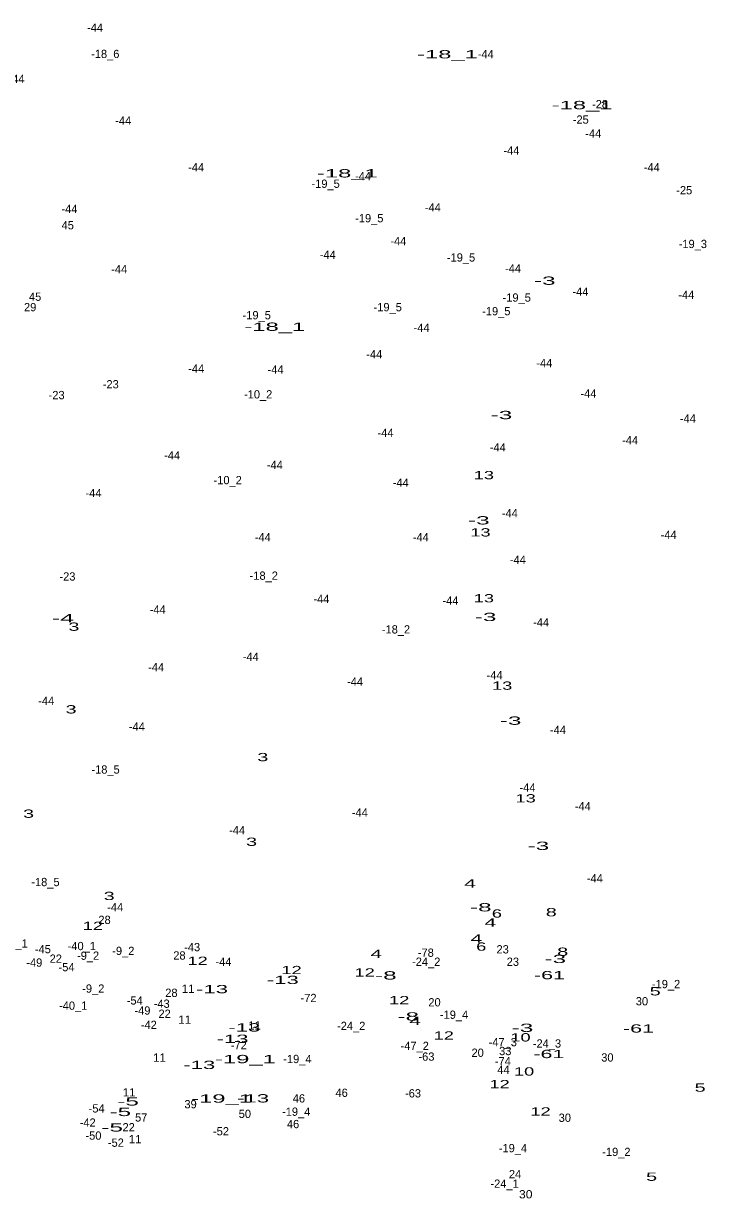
# Model space of a CAD drawing. Extents: x -657046 to -655830, y -1000534 to -999433.
# Drawn here: x -656670 to -656340, y -1000534 to -999965 of the extents above; entities that cross this region are included whole.
import ezdxf
from ezdxf.enums import TextEntityAlignment as Align

# ---------------------------------------------------------------- set-up
doc = ezdxf.new("R2010")
doc.units = 0
doc.header["$LTSCALE"] = 1.6
doc.layers.add('24', color=7, linetype='Continuous')

msp = doc.modelspace()

# ---------------------------------------------------------------- texts
at = {"layer": '24'}
for s, p in [('-44', (-656635.773, -999969.48)), ('-18_6', (-656630.842, -999982.2)), ('-44', (-656446.713, -999982.28)), ('-44', (-656673.783, -999994.29)), ('-28', (-656391.415, -1000006.5)), ('-44', (-656622.153, -1000014.48)), ('-25', (-656400.735, -1000013.96)), ('-44', (-656394.693, -1000020.74)), ('-44', (-656434.293, -1000028.9)), ('-44', (-656586.863, -1000037.04)), ('-44', (-656366.353, -1000037.05)), ('-44', (-656506.113, -1000041.31)), ('-19_5', (-656524.202, -1000045)), ('-25', (-656350.655, -1000048.14)), ('-44', (-656648.163, -1000057.2)), ('-19_5', (-656503.072, -1000061.68)), ('-44', (-656472.323, -1000056.45)), ('45', (-656648.991, -1000065.08)), ('-44', (-656489.013, -1000072.76)), ('-19_3', (-656346.492, -1000074.15)), ('-44', (-656523.173, -1000079.36)), ('-19_5', (-656458.672, -1000080.69)), ('-44', (-656624.093, -1000086.33)), ('-44', (-656433.513, -1000085.98)), ('45', (-656664.781, -1000099.67)), ('-19_5', (-656431.722, -1000100.08)), ('-44', (-656400.903, -1000097.25)), ('-44', (-656349.663, -1000098.8)), ('29', (-656667.183, -1000104.72)), ('-19_5', (-656494.152, -1000104.74)), ('-19_5', (-656441.612, -1000106.68)), ('-19_5', (-656557.542, -1000108.62)), ('-44', (-656477.753, -1000114.7)), ('-44', (-656500.663, -1000127.52)), ('-44', (-656586.833, -1000134.48)), ('-44', (-656548.423, -1000134.91)), ('-44', (-656418.373, -1000131.78)), ('-23', (-656628.185, -1000142.04)), ('-10_2', (-656556.85, -1000146.92)), ('-44', (-656397.023, -1000146.54)), ('-23', (-656654.375, -1000147.28)), ('-44', (-656348.883, -1000158.58)), ('-44', (-656495.223, -1000165.58)), ('-44', (-656376.833, -1000169.07)), ('-44', (-656440.893, -1000172.58)), ('-44', (-656598.473, -1000176.43)), ('-44', (-656548.783, -1000181.08)), ('-10_2', (-656571.59, -1000188.42)), ('-44', (-656487.853, -1000189.65)), ('-44', (-656636.523, -1000194.68)), ('-44', (-656435.063, -1000204.43)), ('-44', (-656358.203, -1000214.89)), ('-44', (-656554.603, -1000216.04)), ('-44', (-656478.143, -1000216.05)), ('-44', (-656431.183, -1000226.95)), ('-23', (-656649.145, -1000235.05)), ('-18_2', (-656554.136, -1000234.66)), ('-44', (-656526.273, -1000245.94)), ('-44', (-656463.783, -1000246.73)), ('-44', (-656605.463, -1000251)), ('-18_2', (-656490.156, -1000260.65)), ('-44', (-656419.923, -1000257.24)), ('-44', (-656560.433, -1000273.9)), ('-44', (-656606.233, -1000278.96)), ('-44', (-656442.433, -1000282.82)), ('-44', (-656509.963, -1000285.94)), ('-44', (-656659.423, -1000295.26)), ('-44', (-656615.553, -1000307.7)), ('-44', (-656411.773, -1000309.28)), ('-18_5', (-656630.696, -1000328.45)), ('-44', (-656426.513, -1000337.19)), ('-44', (-656507.633, -1000349.24)), ('-44', (-656399.743, -1000346.17)), ('-44', (-656567.033, -1000357.79)), ('-18_5', (-656659.776, -1000382.91)), ('-44', (-656393.913, -1000381.1)), ('-44', (-656626.033, -1000395.07)), ('28', (-656631.187, -1000401.22)), ('-40_1', (-656675.194, -1000412.62)), ('-40_1', (-656642.204, -1000413.88)), ('-45', (-656661.039, -1000415.37)), ('22', (-656654.787, -1000419.99)), ('-9_2', (-656639.159, -1000418.54)), ('-9_2', (-656622.099, -1000416.22)), ('-9_2', (-656622.099, -1000416.22)), ('28', (-656594.947, -1000418.43)), ('-43', (-656588.779, -1000414.4)), ('-78', (-656475.721, -1000417.1)), ('23', (-656438.537, -1000415.47)), ('-49', (-656665.175, -1000421.88)), ('-54', (-656649.579, -1000424.09)), ('-44', (-656573.633, -1000421.48)), ('-24_2', (-656475.537, -1000421.47)), ('23', (-656433.587, -1000421.48)), ('-9_2', (-656636.639, -1000434.45)), ('28', (-656598.827, -1000436.51)), ('-19_2', (-656359.452, -1000432.28)), ('-40_1', (-656646.374, -1000442.72)), ('-54', (-656616.579, -1000440.21)), ('-43', (-656603.529, -1000441.78)), ('-72', (-656532.461, -1000439.02)), ('20', (-656471.521, -1000441.1)), ('30', (-656371.131, -1000440.58)), ('-49', (-656612.855, -1000445.08)), ('22', (-656602.107, -1000446.64)), ('-19_4', (-656462.056, -1000447.1)), ('-42', (-656609.779, -1000452.02)), ('-24_2', (-656511.837, -1000452.53)), ('-72', (-656566.231, -1000461.83)), ('-47_2', (-656481.082, -1000462.18)), ('20', (-656450.621, -1000465.5)), ('-47_3', (-656438.462, -1000460.37)), ('33', (-656437.277, -1000464.68)), ('-24_3', (-656417.097, -1000461.03)), ('-19_4', (-656537.866, -1000468.53)), ('-63', (-656475.41, -1000467.38)), ('-74', (-656438.435, -1000469.58)), ('30', (-656387.851, -1000467.8)), ('44', (-656438.166, -1000473.76)), ('46', (-656537.137, -1000487.6)), ('46', (-656516.457, -1000484.88)), ('-63', (-656481.91, -1000485.15)), ('-54', (-656635.019, -1000492.44)), ('39', (-656589.553, -1000490.41)), ('-42', (-656639.339, -1000499.3)), ('57', (-656613.433, -1000496.81)), ('50', (-656563.281, -1000495.09)), ('-19_4', (-656538.446, -1000494.03)), ('30', (-656408.451, -1000496.96)), ('22', (-656619.507, -1000501.56)), ('-52', (-656574.845, -1000503.51)), ('46', (-656539.947, -1000500.02)), ('-50', (-656636.559, -1000505.59)), ('-52', (-656625.705, -1000509.02)), ('-19_4', (-656433.556, -1000511.68)), ('-19_2', (-656383.492, -1000513.49)), ('24', (-656432.531, -1000524.24)), ('-24_1', (-656437.6, -1000528.87))]:
    msp.add_text(s, height=4, dxfattribs=at).set_placement(p, align=Align.CENTER)
for s, width, p in [('-18_1', 2.15, (-656465.227, -999982.36)), ('-18_1', 2.15, (-656400.087, -1000006.95)), ('-18_1', 2.15, (-656513.697, -1000039.96)), ('-3', 2.2, (-656418.154, -1000091.93)), ('-18_1', 2.15, (-656548.787, -1000114.2)), ('-3', 2.2, (-656439.104, -1000156.93)), ('13', 1.65, (-656447.617, -1000186)), ('-3', 2.2, (-656450.064, -1000207.88)), ('13', 1.65, (-656449.277, -1000213.7)), ('13', 1.65, (-656447.617, -1000245.58)), ('-3', 2.2, (-656446.794, -1000254.62)), ('-4', 2.25, (-656651.3, -1000255.28)), ('3', 1.8, (-656646.031, -1000259.34)), ('13', 1.65, (-656438.777, -1000287.87)), ('3', 1.8, (-656647.391, -1000299.34)), ('-3', 2.2, (-656434.684, -1000304.81)), ('3', 1.8, (-656554.601, -1000322.45)), ('13', 1.65, (-656427.417, -1000342.4)), ('3', 1.8, (-656667.961, -1000349.83)), ('3', 1.8, (-656560.041, -1000363.42)), ('-3', 2.2, (-656421.224, -1000365.39)), ('4', 1.9, (-656454.287, -1000383.59)), ('3', 1.8, (-656628.951, -1000389.63)), ('-8', 2.2, (-656449.114, -1000395.12)), ('4', 1.9, (-656444.487, -1000402.52)), ('6', 1.65, (-656441.316, -1000398.12)), ('8', 1.8, (-656415.001, -1000397.5)), ('12', 1.65, (-656636.877, -1000404.1)), ('4', 1.9, (-656451.187, -1000410.29)), ('6', 1.65, (-656448.886, -1000414.14)), ('4', 1.9, (-656499.697, -1000417.67)), ('8', 1.8, (-656409.481, -1000416.64)), ('12', 1.65, (-656586.157, -1000421.01)), ('12', 1.65, (-656540.677, -1000425.49)), ('-3', 2.2, (-656413.074, -1000420.1)), ('-13', 2, (-656544.931, -1000430.26)), ('12', 1.65, (-656505.307, -1000426.65)), ('-8', 2.2, (-656495.064, -1000428.09)), ('-61', 1.95, (-656415.875, -1000427.95)), ('11', 1.05, (-656590.734, -1000434.53)), ('-13', 2, (-656579.151, -1000434.72)), ('5', 1.8, (-656364.711, -1000435.78)), ('12', 1.65, (-656488.597, -1000440.06)), ('-8', 2.2, (-656484.204, -1000447.97)), ('11', 1.05, (-656592.384, -1000449.5)), ('-13', 2, (-656563.541, -1000453.25)), ('11', 1.05, (-656558.574, -1000452.32)), ('4', 1.9, (-656480.877, -1000450.1)), ('-3', 2.2, (-656428.914, -1000453.46)), ('-61', 1.95, (-656372.785, -1000453.77)), ('-13', 2, (-656569.261, -1000458.77)), ('12', 1.65, (-656467.027, -1000457.17)), ('10', 1.65, (-656429.914, -1000458.06)), ('11', 1.05, (-656604.634, -1000467.88)), ('-19_1', 2.15, (-656563.013, -1000468.57)), ('-61', 1.95, (-656416.165, -1000466.11)), ('-13', 2, (-656585.351, -1000471.38)), ('10', 1.65, (-656428.164, -1000474.57)), ('12', 1.65, (-656440.017, -1000480.69)), ('5', 1.8, (-656342.971, -1000482.38)), ('11', 1.05, (-656619.294, -1000484.69)), ('-19_1', 2.15, (-656574.553, -1000487.66)), ('-13', 2, (-656559.281, -1000487.57)), ('-5', 2.2, (-656619.794, -1000489.07)), ('12', 1.65, (-656420.187, -1000493.91)), ('-5', 2.2, (-656623.544, -1000494.16)), ('-5', 2.2, (-656627.484, -1000501.66)), ('11', 1.05, (-656616.384, -1000507.33)), ('5', 1.8, (-656366.451, -1000525.49)), ('30', 1.1, (-656427.37, -1000533.99))]:
    msp.add_text(s, height=4, dxfattribs=dict(at, width=width)).set_placement(p, align=Align.CENTER)

doc.saveas('drawing.dxf')
